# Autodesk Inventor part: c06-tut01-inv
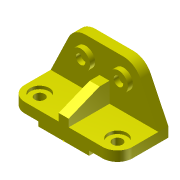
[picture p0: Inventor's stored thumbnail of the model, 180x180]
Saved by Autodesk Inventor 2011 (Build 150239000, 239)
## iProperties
Created: 2010-03
Part Number: c06-tut01-inv
Document SubType Name: Modeling
Designer: CADSoft
Density: 1 g/cm^3
Author: CADSoft
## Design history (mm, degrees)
sketch "Sketch1"
  geometry: 1 further point
sketch "Sketch2"
  geometry: L1 (108, 29)-(-108, 29); L2 (-108, 29)-(-108, 9); L3 (108, 9)-(108, 29); L4 (51, 9)-(51, 0); L5 (51, 0)-(-51, 0); L6 (-51, 0)-(-51, 9); L7 (-108, 9)-(-51, 9); L8 (51, 9)-(108, 9); 1 further point
  constraints: 16 end point, 4 vertical, 3 horizontal, 2 equal length, 1 midpoint
  dimensions: "d0" = 20 distance of L3.start L1.start; "d1" = 29 distance between parallel lines of L5 L1; "d2" = 102 distance of L4.end L5.end; "d3" = 57 distance of L4.start L3.start
extrude "Extrusion1" new body sketch "Sketch2" distance "d5" = 102; taper "d6" = 0 deg
sketch "Sketch3"
  geometry: L1 (108, -29)-(-108, -29) reference; L2 (108, -29)-(72.256, -103.447); L3 (38, -125)-(-38, -125); L4 (-72.256, -103.447)-(-108, -29); A1 r 38 centre (38, -87) between (38, -125) and (72.256, -103.447); A2 r 38 centre (-38, -87) between (-72.256, -103.447) and (-38, -125); 1 further point
  constraints: 6 end point, 4 point on circle, 4 tangent, 2 centre point, 1 equal length, 1 equal radius, 1 horizontal
  dimensions: "d9" = 96 distance between parallel lines of L1 L3; "d10" = 38 radius of A1; "d12" = 76 distance of A2.centre A1.centre
extrude "Extrusion2" join sketch "Sketch3" distance "d14" = 20; taper "d15" = 0 deg
sketch "Sketch4"
  geometry: C1 r 19 at (38, 87); C2 r 9.5 at (38, 87); C3 r 19 at (-38, 87); C4 r 9.5 at (-38, 87); A1 r 38 centre (-38, 87) between (-38, 125) and (-72.256, 103.447) reference; A2 r 38 centre (38, 87) between (72.256, 103.447) and (38, 125) reference; 1 further point
  constraints: 4 centre point, 4 coincident, 2 equal radius
  dimensions: "d16" = 38 diameter of C3; "d17" = 19 diameter of C4
extrude "Extrusion3" join sketch "Sketch4" distance "d18" = 10; taper "d19" = 0 deg
fillet "Fillet1" dims "d20" = 30
hole "Hole1" diameter "d23" = 20; stored, may be unused: countersink angle "d27" = 90 deg, drill point angle "d29" = 118 deg; dims "d21" = 10, "d22" = 10, "d24" = 6, "d25" = 38, "d26" = 6, "d28" = 8
hole "Hole2" diameter "d32" = 20; stored, may be unused: countersink angle "d36" = 90 deg, drill point angle "d38" = 118 deg; dims "d30" = 10, "d31" = 10, "d33" = 6, "d34" = 38, "d35" = 6, "d37" = 8
workplane "Work Plane1"
sketch "Sketch5"
  geometry: L1 (-40, 0)-(-40, -20); L2 (-40, -20)-(-15, -82); L3 (-15, -82)-(0, -82); L4 (-74.447, 0)-(0, 0) reference; L5 (0, -52)-(0, 0) reference; 2 further points
  constraints: 6 end point, 1 coincident, 1 point on line
  dimensions: "d40" = 40 distance between parallel lines of L5 L1; "d41" = 15 distance of L2.end L3.end; "d42" = 20 distance of L1.start L1.end
feature "Rib1" sketch "Sketch5" dims "d43" = 1, "d44" = 20, "d45" = 0
body "Solid1"
other parameters: "d39" = -108
